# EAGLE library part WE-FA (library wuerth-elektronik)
SMD EMI Suppression Ferrite Bead Arrays WE-FA - 4 SMD ferrites in one component - Broadband screening because of the core material NiZn - Extremely low cross talk
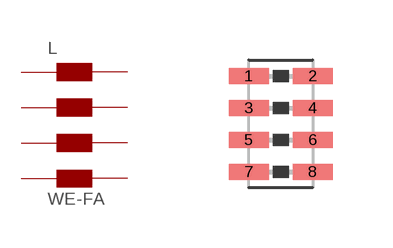
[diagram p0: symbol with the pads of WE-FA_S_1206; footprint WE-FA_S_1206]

Designator prefix L

## WE-FA  [WE-FA_S_1206]
1  8  pas
2  7  pas
3  6  pas
4  5  pas
5  4  pas
6  3  pas
7  2  pas
8  1  pas

## Footprint WE-FA_S_1206 (pad centres in mm)
SMD EMI Supression Ferrite Bead Array
smd 1 x 0.4: 1 -2.07,1.2; 2 -0.47,1.2; 3 -2.07,0.4; 4 -0.47,0.4; 5 -2.07,-0.4; 6 -0.47,-0.4; 7 -2.07,-1.2; 8 -0.47,-1.2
